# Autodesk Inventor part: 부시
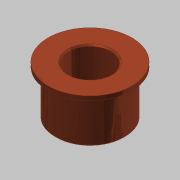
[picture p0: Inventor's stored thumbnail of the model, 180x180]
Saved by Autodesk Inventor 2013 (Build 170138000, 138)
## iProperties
Created: 2015-10
Part Number: 부시
Document SubType Name: Modeling
Designer: mdu
Density: 7.86 g/cm^3
Material: 강철, 연강
Mass: 364.706 g
Surface Area: 129.307 cm^2
Volume: 46.4003 cm^3
Author: mdu
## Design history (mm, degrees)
sketch "스케치1"
  geometry: C1 r 31 at (0, 0) reference; C2 r 25 at (0, 0) reference; C3 r 30 at (0, 0) reference; 1 further point
  node "참조1"
  node "참조2"
  node "참조4"
extrude "돌출1" new body sketch "스케치1" distance "d0" = 3; taper "d1" = 0 deg
extrude "돌출2" join sketch "스케치1" distance "d2" = 35; taper "d3" = 0 deg
chamfer "모따기1" distance "d6" = 1; stored, may be unused: second distance "d7" = 2, angle "d8" = 45 deg
sketch "스케치3"
  geometry: C1 r 15 at (0, 0); 1 further point
  constraints: 1 centre point, 1 coincident
  dimensions: "d13" = 30 diameter of C1
extrude "돌출4" cut sketch "스케치3" stored distance "d14" = 10; taper "d15" = 0 deg
chamfer "모따기3" distance "d16" = 1; stored, may be unused: second distance "d17" = 2, angle "d18" = 45 deg
node "솔리드1"
